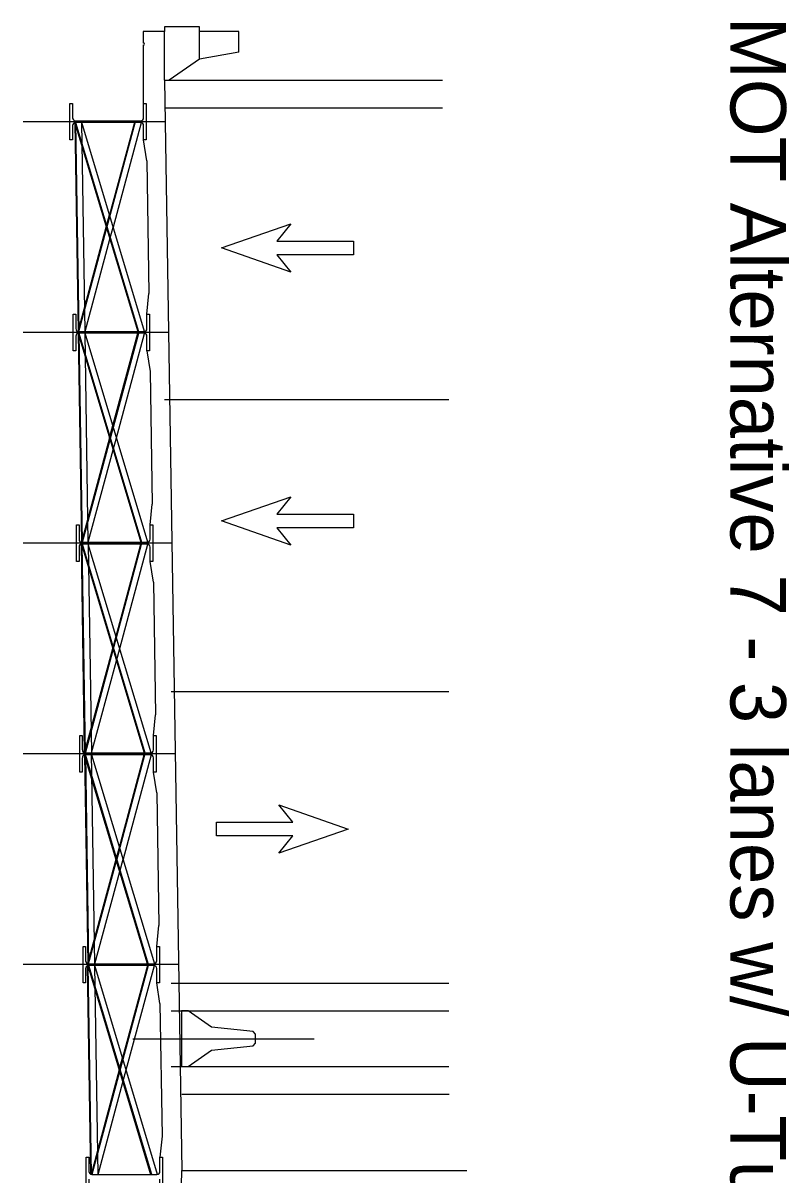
# Model space of a CAD drawing. Extents: x 9107 to 9297, y 5920 to 6248.
# Drawn here: x 9269.87 to 9297.45, y 6078.61 to 6120.06 of the extents above; entities that cross this region are included whole.
import ezdxf

# ---------------------------------------------------------------- set-up
doc = ezdxf.new("R2010")
doc.units = 0
for name, color, linetype in [('BR_P_Beam_Hidden', 7, 'Continuous'), ('BR_P_Dia_Hidden', 7, 'Continuous'), ('BR_X_Beam_Centerline', 7, 'Continuous'), ('BR_X_Beam_Object', 7, 'Continuous'), ('BR_X_Dia_Hidden', 7, 'Continuous'), ('BR_X_Dia_Object', 7, 'Continuous'), ('BR_X_Rail_Centerline', 7, 'Continuous'), ('BR_X_Rail_Const_Joint', 7, 'Continuous'), ('BR_X_Rail_Object', 7, 'Continuous'), ('BR_X_Slab_Centerline', 7, 'Continuous'), ('BR_X_Slab_Object', 7, 'Continuous'), ('SC_Scratch2', 7, 'Continuous'), ('SC_Scratch3', 7, 'Continuous')]:
    doc.layers.add(name, color=color, linetype=linetype)

msp = doc.modelspace()

# ---------------------------------------------------------------- linework, layer by layer
at = {"layer": 'BR_P_Beam_Hidden'}
msp.add_line((9275.584, 6078.761), (9285.852, 6078.761), dxfattribs=at)
at = {"layer": 'BR_P_Dia_Hidden'}
for p, q in [((9277.014, 6111.967), (9279.514, 6112.835)), ((9279.514, 6112.835), (9279.014, 6112.217)), ((9279.014, 6112.217), (9281.764, 6112.217)), ((9281.764, 6112.217), (9281.764, 6111.717)), ((9277.014, 6111.967), (9277.014, 6111.967)), ((9279.514, 6111.099), (9277.014, 6111.967)), ((9281.764, 6111.967), (9281.764, 6111.967)), ((9281.764, 6111.717), (9279.014, 6111.717)), ((9279.014, 6111.717), (9279.514, 6111.099)), ((9277.014, 6102.142), (9279.514, 6103.01)), ((9279.514, 6103.01), (9279.014, 6102.392)), ((9279.014, 6102.392), (9281.764, 6102.392)), ((9281.764, 6102.392), (9281.764, 6101.892)), ((9277.014, 6102.142), (9277.014, 6102.142)), ((9279.514, 6101.274), (9277.014, 6102.142)), ((9281.764, 6101.892), (9279.014, 6101.892)), ((9279.014, 6101.892), (9279.514, 6101.274)), ((9281.764, 6102.142), (9281.764, 6102.142)), ((9279.583, 6091.305), (9279.083, 6091.923)), ((9279.083, 6091.923), (9281.583, 6091.055)), ((9276.833, 6090.805), (9276.833, 6091.305)), ((9276.833, 6091.305), (9279.583, 6091.305)), ((9276.833, 6091.055), (9276.833, 6091.055)), ((9281.583, 6091.055), (9279.083, 6090.187)), ((9281.583, 6091.055), (9281.583, 6091.055)), ((9279.583, 6090.805), (9276.833, 6090.805)), ((9279.083, 6090.187), (9279.583, 6090.805))]:
    msp.add_line(p, q, dxfattribs=at)
at = {"layer": 'BR_X_Beam_Centerline'}
for p, q in [((9274.97, 6118.011), (9284.97, 6118.011)), ((9274.97, 6118.011), (9284.97, 6118.011)), ((9274.97, 6117.011), (9284.97, 6117.011)), ((9274.97, 6117.011), (9284.97, 6117.011)), ((9274.97, 6117.011), (9284.97, 6117.011)), ((9274.97, 6117.011), (9284.97, 6117.011)), ((9274.97, 6106.511), (9284.97, 6106.511)), ((9274.97, 6106.511), (9284.97, 6106.511)), ((9274.97, 6106.511), (9284.97, 6106.511)), ((9274.97, 6106.511), (9284.97, 6106.511)), ((9275.205, 6106.511), (9285.205, 6106.511)), ((9275.205, 6106.511), (9285.205, 6106.511)), ((9275.205, 6096.011), (9285.205, 6096.011)), ((9275.205, 6096.011), (9285.205, 6096.011)), ((9275.205, 6085.511), (9285.205, 6085.511)), ((9275.205, 6085.511), (9285.205, 6085.511)), ((9275.205, 6084.511), (9285.205, 6084.511)), ((9275.205, 6084.511), (9285.205, 6084.511)), ((9275.205, 6082.511), (9285.205, 6082.511)), ((9275.588, 6081.511), (9285.213, 6081.511))]:
    msp.add_line(p, q, dxfattribs=at)
at = {"layer": 'BR_X_Beam_Object'}
for p, q in [((9271.759, 6116.542), (9274.103, 6116.542)), ((9271.759, 6116.542), (9274.103, 6116.542)), ((9274.103, 6116.48), (9271.759, 6116.48)), ((9274.103, 6116.48), (9271.759, 6116.48)), ((9271.878, 6108.959), (9274.222, 6108.959)), ((9271.878, 6108.959), (9274.222, 6108.959)), ((9274.222, 6108.896), (9271.878, 6108.896)), ((9274.222, 6108.896), (9271.878, 6108.896)), ((9271.996, 6101.375), (9274.34, 6101.375)), ((9271.996, 6101.375), (9274.34, 6101.375)), ((9274.34, 6101.313), (9271.996, 6101.313)), ((9274.34, 6101.313), (9271.996, 6101.313)), ((9272.115, 6093.792), (9274.459, 6093.792)), ((9272.115, 6093.792), (9274.459, 6093.792)), ((9274.459, 6093.73), (9272.115, 6093.73)), ((9274.459, 6093.73), (9272.115, 6093.73)), ((9272.233, 6086.209), (9274.577, 6086.209)), ((9272.233, 6086.209), (9274.577, 6086.209)), ((9274.577, 6086.146), (9272.233, 6086.146)), ((9274.577, 6086.146), (9272.233, 6086.146)), ((9272.347, 6078.625), (9274.69, 6078.625)), ((9272.347, 6078.625), (9274.69, 6078.625))]:
    msp.add_line(p, q, dxfattribs=at)
for points in [[(9271.65, 6116.37), (9271.65, 6115.855), (9271.556, 6115.855), (9271.556, 6117.167), (9271.65, 6117.167), (9271.65, 6116.651)], [(9271.65, 6116.37), (9271.65, 6115.855), (9271.556, 6115.855), (9271.556, 6117.167), (9271.65, 6117.167), (9271.65, 6116.651)], [(9274.213, 6116.651), (9274.213, 6117.167), (9274.306, 6117.167), (9274.306, 6115.855), (9274.213, 6115.855), (9274.213, 6116.37)], [(9274.213, 6116.651), (9274.213, 6117.167), (9274.306, 6117.167), (9274.306, 6115.855), (9274.213, 6115.855), (9274.213, 6116.37)], [(9271.769, 6108.787), (9271.769, 6108.271), (9271.675, 6108.271), (9271.675, 6109.584), (9271.769, 6109.584), (9271.769, 6109.068)], [(9271.769, 6108.787), (9271.769, 6108.271), (9271.675, 6108.271), (9271.675, 6109.584), (9271.769, 6109.584), (9271.769, 6109.068)], [(9274.331, 6109.068), (9274.331, 6109.584), (9274.425, 6109.584), (9274.425, 6108.271), (9274.331, 6108.271), (9274.331, 6108.787)], [(9274.331, 6109.068), (9274.331, 6109.584), (9274.425, 6109.584), (9274.425, 6108.271), (9274.331, 6108.271), (9274.331, 6108.787)], [(9271.887, 6101.204), (9271.887, 6100.688), (9271.793, 6100.688), (9271.793, 6102), (9271.887, 6102), (9271.887, 6101.485)], [(9271.887, 6101.204), (9271.887, 6100.688), (9271.793, 6100.688), (9271.793, 6102), (9271.887, 6102), (9271.887, 6101.485)], [(9274.45, 6101.485), (9274.45, 6102), (9274.543, 6102), (9274.543, 6100.688), (9274.45, 6100.688), (9274.45, 6101.204)], [(9274.45, 6101.485), (9274.45, 6102), (9274.543, 6102), (9274.543, 6100.688), (9274.45, 6100.688), (9274.45, 6101.204)], [(9272.005, 6093.62), (9272.005, 6093.105), (9271.912, 6093.105), (9271.912, 6094.417), (9272.005, 6094.417), (9272.005, 6093.901)], [(9272.005, 6093.62), (9272.005, 6093.105), (9271.912, 6093.105), (9271.912, 6094.417), (9272.005, 6094.417), (9272.005, 6093.901)], [(9274.568, 6093.901), (9274.568, 6094.417), (9274.662, 6094.417), (9274.662, 6093.105), (9274.568, 6093.105), (9274.568, 6093.62)], [(9274.568, 6093.901), (9274.568, 6094.417), (9274.662, 6094.417), (9274.662, 6093.105), (9274.568, 6093.105), (9274.568, 6093.62)], [(9272.124, 6086.037), (9272.124, 6085.521), (9272.03, 6085.521), (9272.03, 6086.834), (9272.124, 6086.834), (9272.124, 6086.318)], [(9272.124, 6086.037), (9272.124, 6085.521), (9272.03, 6085.521), (9272.03, 6086.834), (9272.124, 6086.834), (9272.124, 6086.318)], [(9274.686, 6086.318), (9274.686, 6086.834), (9274.78, 6086.834), (9274.78, 6085.521), (9274.686, 6085.521), (9274.686, 6086.037)], [(9274.686, 6086.318), (9274.686, 6086.834), (9274.78, 6086.834), (9274.78, 6085.521), (9274.686, 6085.521), (9274.686, 6086.037)], [(9272.237, 6078.454), (9272.237, 6077.938), (9272.144, 6077.938), (9272.144, 6079.25), (9272.237, 6079.25), (9272.237, 6078.735)], [(9272.237, 6078.454), (9272.237, 6077.938), (9272.144, 6077.938), (9272.144, 6079.25), (9272.237, 6079.25), (9272.237, 6078.735)], [(9274.8, 6078.735), (9274.8, 6079.25), (9274.894, 6079.25), (9274.894, 6077.938), (9274.8, 6077.938), (9274.8, 6078.454)], [(9274.8, 6078.735), (9274.8, 6079.25), (9274.894, 6079.25), (9274.894, 6077.938), (9274.8, 6077.938), (9274.8, 6078.454)]]:
    msp.add_lwpolyline(points, dxfattribs=at)
for centre, start, end in [((9271.759, 6116.651), 180, 270), ((9271.759, 6116.651), 180, 270), ((9271.759, 6116.37), 90, 180), ((9271.759, 6116.37), 90, 180), ((9274.103, 6116.651), 270, 360), ((9274.103, 6116.651), 270, 360), ((9274.103, 6116.37), 0, 90), ((9274.103, 6116.37), 0, 90), ((9271.878, 6109.068), 180, 270), ((9271.878, 6109.068), 180, 270), ((9271.878, 6108.787), 90, 180), ((9271.878, 6108.787), 90, 180), ((9274.222, 6109.068), 270, 360), ((9274.222, 6109.068), 270, 360), ((9274.222, 6108.787), 0, 90), ((9274.222, 6108.787), 0, 90), ((9271.996, 6101.485), 180, 270), ((9271.996, 6101.485), 180, 270), ((9274.34, 6101.485), 270, 360), ((9274.34, 6101.485), 270, 360), ((9271.996, 6101.204), 90, 180), ((9271.996, 6101.204), 90, 180), ((9274.34, 6101.204), 0, 90), ((9274.34, 6101.204), 0, 90), ((9272.115, 6093.901), 180, 270), ((9272.115, 6093.901), 180, 270), ((9272.115, 6093.62), 90, 180), ((9272.115, 6093.62), 90, 180), ((9274.459, 6093.901), 270, 360), ((9274.459, 6093.901), 270, 360), ((9274.459, 6093.62), 0, 90), ((9274.459, 6093.62), 0, 90), ((9272.233, 6086.318), 180, 270), ((9272.233, 6086.318), 180, 270), ((9272.233, 6086.037), 90, 180), ((9272.233, 6086.037), 90, 180), ((9274.577, 6086.318), 270, 360), ((9274.577, 6086.318), 270, 360), ((9274.577, 6086.037), 0, 90), ((9274.577, 6086.037), 0, 90), ((9272.347, 6078.735), 180, 270), ((9272.347, 6078.735), 180, 270), ((9274.69, 6078.735), 270, 360), ((9274.69, 6078.735), 270, 360)]:
    msp.add_arc(centre, 0.109, start, end, dxfattribs=at)
at = {"layer": 'BR_X_Dia_Hidden'}
for p, q in [((9271.733, 6116.476), (9271.852, 6108.962)), ((9271.733, 6116.476), (9273.998, 6108.959)), ((9271.733, 6116.476), (9271.852, 6108.962)), ((9271.733, 6116.476), (9273.998, 6108.959)), ((9271.758, 6116.484), (9274.023, 6108.966)), ((9271.758, 6116.484), (9274.023, 6108.966)), ((9271.759, 6116.477), (9271.878, 6108.962)), ((9271.759, 6116.477), (9271.878, 6108.962)), ((9272.102, 6108.959), (9271.983, 6116.48)), ((9274.248, 6108.962), (9271.983, 6116.48)), ((9272.102, 6108.959), (9271.983, 6116.48)), ((9274.248, 6108.962), (9271.983, 6116.48)), ((9273.879, 6116.48), (9272.984, 6113.159)), ((9273.879, 6116.48), (9272.984, 6113.159)), ((9274.129, 6116.476), (9273.116, 6112.72)), ((9274.129, 6116.476), (9273.116, 6112.72)), ((9271.852, 6108.962), (9272.865, 6112.719)), ((9271.852, 6108.962), (9272.865, 6112.719)), ((9272.102, 6108.959), (9272.997, 6112.28)), ((9272.102, 6108.959), (9272.997, 6112.28)), ((9271.852, 6108.896), (9271.97, 6101.379)), ((9271.852, 6108.896), (9274.116, 6101.375)), ((9271.852, 6108.896), (9271.97, 6101.379)), ((9271.852, 6108.896), (9274.116, 6101.375)), ((9271.877, 6108.904), (9274.141, 6101.383)), ((9271.877, 6108.904), (9274.141, 6101.383)), ((9271.878, 6108.897), (9271.996, 6101.379)), ((9271.878, 6108.897), (9271.996, 6101.379)), ((9272.22, 6101.375), (9272.102, 6108.896)), ((9274.366, 6101.379), (9272.102, 6108.896)), ((9272.22, 6101.375), (9272.102, 6108.896)), ((9274.366, 6101.379), (9272.102, 6108.896)), ((9273.102, 6105.575), (9273.998, 6108.896)), ((9273.102, 6105.575), (9273.998, 6108.896)), ((9273.234, 6105.136), (9274.248, 6108.893)), ((9273.234, 6105.136), (9274.248, 6108.893)), ((9272.984, 6105.137), (9271.97, 6101.379)), ((9272.984, 6105.137), (9271.97, 6101.379)), ((9272.22, 6101.375), (9273.116, 6104.697)), ((9272.22, 6101.375), (9273.116, 6104.697)), ((9271.97, 6101.31), (9274.235, 6093.792)), ((9272.089, 6093.795), (9271.97, 6101.31)), ((9271.97, 6101.31), (9274.235, 6093.792)), ((9272.089, 6093.795), (9271.97, 6101.31)), ((9271.995, 6101.317), (9274.26, 6093.8)), ((9271.995, 6101.317), (9274.26, 6093.8)), ((9272.115, 6093.796), (9271.996, 6101.31)), ((9272.115, 6093.796), (9271.996, 6101.31)), ((9274.485, 6093.795), (9272.22, 6101.313)), ((9272.22, 6101.313), (9272.339, 6093.792)), ((9274.485, 6093.795), (9272.22, 6101.313)), ((9272.22, 6101.313), (9272.339, 6093.792)), ((9273.221, 6097.992), (9274.116, 6101.313)), ((9273.221, 6097.992), (9274.116, 6101.313)), ((9273.353, 6097.553), (9274.366, 6101.31)), ((9273.353, 6097.553), (9274.366, 6101.31)), ((9272.089, 6093.795), (9273.102, 6097.552)), ((9272.089, 6093.795), (9273.102, 6097.552)), ((9272.339, 6093.792), (9273.234, 6097.113)), ((9272.339, 6093.792), (9273.234, 6097.113)), ((9272.089, 6093.726), (9272.207, 6086.212)), ((9274.353, 6086.209), (9272.089, 6093.726)), ((9272.089, 6093.726), (9272.207, 6086.212)), ((9274.353, 6086.209), (9272.089, 6093.726)), ((9274.378, 6086.216), (9272.114, 6093.734)), ((9274.378, 6086.216), (9272.114, 6093.734)), ((9272.115, 6093.727), (9272.233, 6086.212)), ((9272.115, 6093.727), (9272.233, 6086.212)), ((9272.457, 6086.209), (9272.339, 6093.792)), ((9272.457, 6086.209), (9272.339, 6093.792)), ((9272.339, 6093.73), (9274.603, 6086.209)), ((9272.339, 6093.73), (9274.603, 6086.209)), ((9273.339, 6090.408), (9274.235, 6093.73)), ((9273.339, 6090.408), (9274.235, 6093.73)), ((9274.485, 6093.726), (9273.471, 6089.968)), ((9274.485, 6093.726), (9273.471, 6089.968)), ((9272.207, 6086.212), (9273.221, 6089.969)), ((9272.207, 6086.212), (9273.221, 6089.969)), ((9272.457, 6086.209), (9273.353, 6089.53)), ((9272.457, 6086.209), (9273.353, 6089.53)), ((9272.181, 6086.146), (9272.295, 6078.628)), ((9272.181, 6086.146), (9272.295, 6078.628)), ((9272.207, 6086.146), (9272.321, 6078.629)), ((9272.207, 6086.146), (9272.321, 6078.629)), ((9272.207, 6086.143), (9274.466, 6078.625)), ((9272.207, 6086.143), (9274.466, 6078.625)), ((9272.232, 6086.151), (9274.491, 6078.633)), ((9272.232, 6086.151), (9274.491, 6078.633)), ((9272.571, 6078.625), (9272.457, 6086.146)), ((9274.716, 6078.629), (9272.457, 6086.146)), ((9272.571, 6078.625), (9272.457, 6086.146)), ((9274.716, 6078.629), (9272.457, 6086.146)), ((9274.353, 6086.146), (9273.455, 6082.825)), ((9274.353, 6086.146), (9273.455, 6082.825)), ((9273.587, 6082.386), (9274.603, 6086.146)), ((9273.587, 6082.386), (9274.603, 6086.146)), ((9273.337, 6082.385), (9272.321, 6078.625)), ((9273.337, 6082.385), (9272.321, 6078.625)), ((9272.571, 6078.625), (9273.468, 6081.946)), ((9272.571, 6078.625), (9273.468, 6081.946))]:
    msp.add_line(p, q, dxfattribs=at)
at = {"layer": 'BR_X_Dia_Object'}
msp.add_line((9276.22, 6118.761), (9276.22, 6119.761), dxfattribs=at)
msp.add_line((9276.22, 6118.761), (9276.22, 6119.761), dxfattribs=at)
at = {"layer": 'BR_X_Rail_Centerline'}
for p, q in [((9276.22, 6119.928), (9274.97, 6119.928)), ((9274.97, 6119.928), (9274.97, 6119.761)), ((9276.22, 6119.928), (9274.97, 6119.928)), ((9274.97, 6119.928), (9274.97, 6119.761)), ((9276.22, 6119.761), (9276.22, 6119.928)), ((9276.22, 6119.761), (9276.22, 6119.928)), ((9277.637, 6119.761), (9276.22, 6119.761)), ((9277.637, 6119.761), (9276.22, 6119.761)), ((9277.637, 6119.011), (9277.637, 6119.761)), ((9277.637, 6119.011), (9277.637, 6119.761)), ((9277.637, 6119.011), (9276.22, 6118.761)), ((9277.637, 6119.011), (9276.22, 6118.761)), ((9276.22, 6118.761), (9275.137, 6118.011)), ((9276.22, 6118.761), (9275.137, 6118.011)), ((9274.97, 6118.011), (9275.137, 6118.011)), ((9274.97, 6118.011), (9275.137, 6118.011))]:
    msp.add_line(p, q, dxfattribs=at)
at = {"layer": 'BR_X_Rail_Const_Joint'}
for p, q in [((9274.97, 6119.761), (9274.2, 6119.761)), ((9274.2, 6119.761), (9274.2, 6119.344)), ((9274.97, 6119.761), (9274.2, 6119.761)), ((9274.2, 6119.761), (9274.2, 6119.344)), ((9274.2, 6119.261), (9274.2, 6116.6)), ((9274.2, 6119.261), (9274.2, 6116.6)), ((9274.97, 6118.011), (9275.584, 6078.761)), ((9274.97, 6118.011), (9275.584, 6078.761)), ((9274.328, 6115.105), (9274.213, 6115.855)), ((9274.328, 6115.105), (9274.213, 6115.855)), ((9274.328, 6115.105), (9274.403, 6110.334)), ((9274.328, 6115.105), (9274.403, 6110.334)), ((9274.331, 6109.584), (9274.403, 6110.334)), ((9274.331, 6109.584), (9274.403, 6110.334)), ((9274.331, 6108.271), (9274.447, 6107.521)), ((9274.331, 6108.271), (9274.447, 6107.521)), ((9274.447, 6107.521), (9274.521, 6102.75)), ((9274.447, 6107.521), (9274.521, 6102.75)), ((9274.45, 6102), (9274.521, 6102.75)), ((9274.45, 6102), (9274.521, 6102.75)), ((9274.565, 6099.938), (9274.45, 6100.688)), ((9274.565, 6099.938), (9274.45, 6100.688)), ((9274.565, 6099.938), (9274.64, 6095.167)), ((9274.565, 6099.938), (9274.64, 6095.167)), ((9274.568, 6094.417), (9274.64, 6095.167)), ((9274.568, 6094.417), (9274.64, 6095.167)), ((9274.684, 6092.355), (9274.568, 6093.105)), ((9274.684, 6092.355), (9274.568, 6093.105)), ((9274.684, 6092.355), (9274.758, 6087.584)), ((9274.684, 6092.355), (9274.758, 6087.584)), ((9274.686, 6086.834), (9274.758, 6087.584)), ((9274.686, 6086.834), (9274.758, 6087.584)), ((9274.802, 6084.771), (9274.686, 6085.521)), ((9274.802, 6084.771), (9274.686, 6085.521)), ((9274.802, 6084.771), (9274.877, 6080)), ((9274.802, 6084.771), (9274.877, 6080)), ((9274.877, 6080), (9274.8, 6079.25)), ((9274.877, 6080), (9274.8, 6079.25)), ((9274.97, 6039.511), (9275.584, 6078.761))]:
    msp.add_line(p, q, dxfattribs=at)
msp.add_arc((9274.2, 6119.303), 0.0417, 270, 90, dxfattribs=at)
msp.add_arc((9274.2, 6119.303), 0.0417, 270, 90, dxfattribs=at)
at = {"layer": 'BR_X_Rail_Object'}
msp.add_line((9274.97, 6118.011), (9274.97, 6119.761), dxfattribs=at)
msp.add_line((9274.97, 6118.011), (9274.97, 6119.761), dxfattribs=at)
at = {"layer": 'BR_X_Slab_Centerline'}
for p, q in [((9275.822, 6084.511), (9275.572, 6084.511)), ((9275.572, 6084.511), (9275.572, 6082.511)), ((9276.655, 6083.928), (9275.822, 6084.511)), ((9278.156, 6083.77), (9276.655, 6083.928)), ((9278.239, 6083.678), (9278.156, 6083.77)), ((9278.239, 6083.344), (9278.239, 6083.678)), ((9276.655, 6083.094), (9278.156, 6083.252)), ((9278.156, 6083.252), (9278.239, 6083.344)), ((9275.822, 6082.511), (9276.655, 6083.094)), ((9275.572, 6082.511), (9275.822, 6082.511))]:
    msp.add_line(p, q, dxfattribs=at)
at = {"layer": 'BR_X_Slab_Object'}
msp.add_line((9273.821, 6083.511), (9280.35, 6083.511), dxfattribs=at)
at = {"layer": 'SC_Scratch2'}
for p, q in [((9274.994, 6116.511), (9269.87, 6116.511)), ((9274.994, 6116.511), (9269.87, 6116.511)), ((9275.112, 6108.928), (9269.87, 6108.928)), ((9275.112, 6108.928), (9269.87, 6108.928)), ((9275.231, 6101.344), (9269.87, 6101.344)), ((9275.231, 6101.344), (9269.87, 6101.344)), ((9275.349, 6093.761), (9269.87, 6093.761)), ((9275.349, 6093.761), (9269.87, 6093.761)), ((9275.468, 6086.178), (9269.87, 6086.178)), ((9275.468, 6086.178), (9269.87, 6086.178))]:
    msp.add_line(p, q, dxfattribs=at)
at = {"layer": 'SC_Scratch3'}
for p, q in [((9271.877, 6108.955), (9273.904, 6116.473)), ((9271.877, 6108.955), (9273.904, 6116.473)), ((9272.865, 6112.719), (9272.984, 6113.159)), ((9272.865, 6112.719), (9272.984, 6113.159)), ((9272.997, 6112.28), (9273.116, 6112.72)), ((9272.997, 6112.28), (9273.116, 6112.72)), ((9274.023, 6108.89), (9271.995, 6101.372)), ((9274.023, 6108.89), (9271.995, 6101.372)), ((9272.984, 6105.137), (9273.102, 6105.575)), ((9272.984, 6105.137), (9273.102, 6105.575)), ((9273.116, 6104.697), (9273.234, 6105.136)), ((9273.116, 6104.697), (9273.234, 6105.136)), ((9272.114, 6093.788), (9274.141, 6101.306)), ((9272.114, 6093.788), (9274.141, 6101.306)), ((9273.102, 6097.552), (9273.221, 6097.992)), ((9273.102, 6097.552), (9273.221, 6097.992)), ((9273.234, 6097.113), (9273.353, 6097.553)), ((9273.234, 6097.113), (9273.353, 6097.553)), ((9273.364, 6090.401), (9274.26, 6093.723)), ((9273.364, 6090.401), (9274.26, 6093.723)), ((9273.221, 6089.969), (9273.339, 6090.408)), ((9273.221, 6089.969), (9273.339, 6090.408)), ((9273.353, 6090.361), (9273.235, 6089.922)), ((9273.353, 6090.361), (9273.235, 6089.922)), ((9272.232, 6086.205), (9273.246, 6089.962)), ((9272.232, 6086.205), (9273.246, 6089.962)), ((9273.353, 6089.53), (9273.471, 6089.968)), ((9273.353, 6089.53), (9273.471, 6089.968)), ((9274.378, 6086.139), (9272.346, 6078.619)), ((9274.378, 6086.139), (9272.346, 6078.619)), ((9273.337, 6082.385), (9273.455, 6082.825)), ((9273.337, 6082.385), (9273.455, 6082.825)), ((9273.468, 6081.946), (9273.587, 6082.386)), ((9273.468, 6081.946), (9273.587, 6082.386))]:
    msp.add_line(p, q, dxfattribs=at)

# ---------------------------------------------------------------- texts
at = {"layer": 'BR_X_Beam_Centerline'}
msp.add_text('MOT Alternative 7 - 3 lanes w/ U-Turns ', height=2, rotation=270, dxfattribs=at).set_placement((9295.343, 6120.281))

doc.saveas('drawing.dxf')
